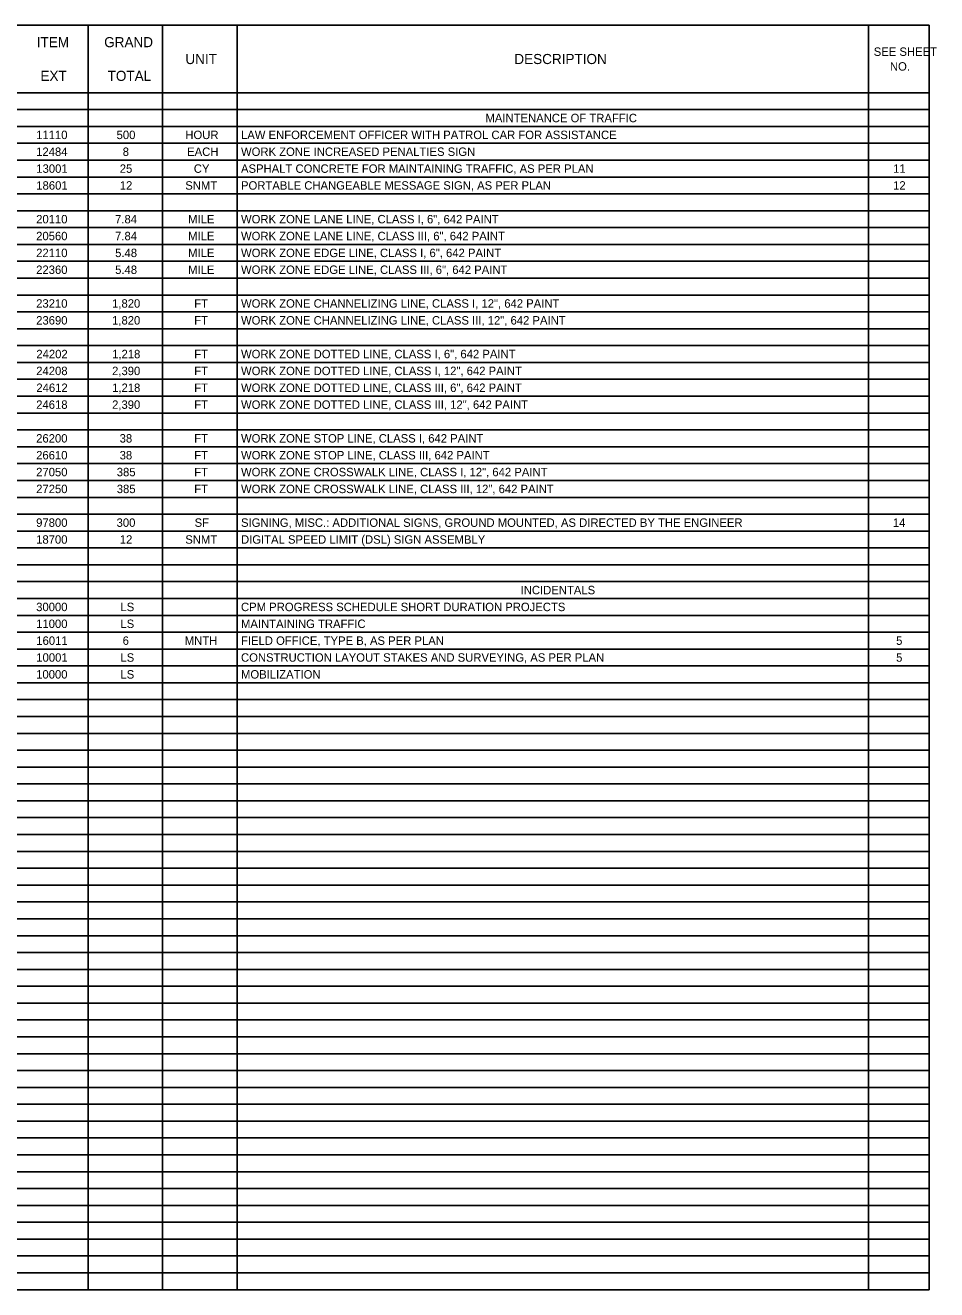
# Model space of a CAD drawing. Extents: x -32.2 to 34, y 0 to 22.
# Drawn here: x -16.7 to -1.56, y 0.5 to 21.5 of the extents above; entities that cross this region are included whole.
import ezdxf

# ---------------------------------------------------------------- set-up
doc = ezdxf.new("R2010")
doc.units = 0
doc.layers.add('SH_Text', color=7, linetype='Continuous')

msp = doc.modelspace()

# ---------------------------------------------------------------- linework, layer by layer
at = {"layer": 'SH_Text'}
for p, q in [((-32.188, 21.5), (-1.685, 21.5)), ((-15.652, 21.5), (-15.652, 0.5)), ((-14.417, 21.5), (-14.417, 0.5)), ((-13.181, 21.5), (-13.181, 0.5)), ((-2.69, 21.5), (-2.69, 0.5)), ((-1.685, 21.5), (-1.685, 0.5)), ((-32.188, 20.38), (-1.685, 20.38)), ((-32.188, 20.1), (-1.685, 20.1)), ((-32.188, 19.82), (-1.685, 19.82)), ((-32.188, 19.54), (-1.685, 19.54)), ((-32.188, 19.26), (-1.685, 19.26)), ((-32.188, 18.98), (-1.685, 18.98)), ((-32.188, 18.7), (-1.685, 18.7)), ((-32.188, 18.42), (-1.685, 18.42)), ((-32.188, 18.14), (-1.685, 18.14)), ((-32.188, 17.86), (-1.685, 17.86)), ((-32.188, 17.58), (-1.685, 17.58)), ((-32.188, 17.3), (-1.685, 17.3)), ((-32.188, 17.02), (-1.685, 17.02)), ((-32.188, 16.74), (-1.685, 16.74)), ((-32.188, 16.46), (-1.685, 16.46)), ((-32.188, 16.18), (-1.685, 16.18)), ((-32.188, 15.9), (-1.685, 15.9)), ((-32.188, 15.62), (-1.685, 15.62)), ((-32.188, 15.34), (-1.685, 15.34)), ((-32.188, 15.06), (-1.685, 15.06)), ((-32.188, 14.78), (-1.685, 14.78)), ((-32.188, 14.5), (-1.685, 14.5)), ((-32.188, 14.22), (-1.685, 14.22)), ((-32.188, 13.94), (-1.685, 13.94)), ((-32.188, 13.66), (-1.685, 13.66)), ((-32.188, 13.38), (-1.685, 13.38)), ((-32.188, 13.1), (-1.685, 13.1)), ((-32.188, 12.82), (-1.685, 12.82)), ((-32.188, 12.54), (-1.685, 12.54)), ((-32.188, 12.26), (-1.685, 12.26)), ((-32.188, 11.98), (-1.685, 11.98)), ((-32.188, 11.7), (-1.685, 11.7)), ((-32.188, 11.42), (-1.685, 11.42)), ((-32.188, 11.14), (-1.685, 11.14)), ((-32.188, 10.86), (-1.685, 10.86)), ((-32.188, 10.58), (-1.685, 10.58)), ((-32.188, 10.3), (-1.685, 10.3)), ((-32.188, 10.02), (-1.685, 10.02)), ((-32.188, 9.74), (-1.685, 9.74)), ((-32.188, 9.46), (-1.685, 9.46)), ((-32.188, 9.18), (-1.685, 9.18)), ((-32.188, 8.9), (-1.685, 8.9)), ((-32.188, 8.62), (-1.685, 8.62)), ((-32.188, 8.34), (-1.685, 8.34)), ((-32.188, 8.06), (-1.685, 8.06)), ((-32.188, 7.78), (-1.685, 7.78)), ((-32.188, 7.5), (-1.685, 7.5)), ((-32.188, 7.22), (-1.685, 7.22)), ((-32.188, 6.94), (-1.685, 6.94)), ((-32.188, 6.66), (-1.685, 6.66)), ((-32.188, 6.38), (-1.685, 6.38)), ((-32.188, 6.1), (-1.685, 6.1)), ((-32.188, 5.82), (-1.685, 5.82)), ((-32.188, 5.54), (-1.685, 5.54)), ((-32.188, 5.26), (-1.685, 5.26)), ((-32.188, 4.98), (-1.685, 4.98)), ((-32.188, 4.7), (-1.685, 4.7)), ((-32.188, 4.42), (-1.685, 4.42)), ((-32.188, 4.14), (-1.685, 4.14)), ((-32.188, 3.86), (-1.685, 3.86)), ((-32.188, 3.58), (-1.685, 3.58)), ((-32.188, 3.3), (-1.685, 3.3)), ((-32.188, 3.02), (-1.685, 3.02)), ((-32.188, 2.74), (-1.685, 2.74)), ((-32.188, 2.46), (-1.685, 2.46)), ((-32.188, 2.18), (-1.685, 2.18)), ((-32.188, 1.9), (-1.685, 1.9)), ((-32.188, 1.62), (-1.685, 1.62)), ((-32.188, 1.34), (-1.685, 1.34)), ((-32.188, 1.06), (-1.685, 1.06)), ((-32.188, 0.78), (-1.685, 0.78)), ((-32.188, 0.5), (-1.685, 0.5))]:
    msp.add_line(p, q, dxfattribs=at)

# ---------------------------------------------------------------- texts
for s, height, p in [('ITEM', 0.168, (-16.508, 21.136)), ('GRAND', 0.168, (-15.388, 21.136)), ('UNIT', 0.168, (-14.039, 20.856)), ('DESCRIPTION', 0.168, (-8.574, 20.856)), ('SEE SHEET ', 0.14, (-2.604, 20.992)), ('NO.', 0.14, (-2.335, 20.747)), ('EXT', 0.168, (-16.447, 20.576)), ('TOTAL', 0.168, (-15.331, 20.576)), ('MAINTENANCE OF TRAFFIC', 0.14, (-9.054, 19.89)), ('11110', 0.14, (-16.518, 19.61)), ('500', 0.14, (-15.182, 19.61)), ('HOUR', 0.14, (-14.04, 19.61)), ('LAW ENFORCEMENT OFFICER WITH PATROL CAR FOR ASSISTANCE', 0.14, (-13.115, 19.61)), ('12484', 0.14, (-16.518, 19.33)), ('8', 0.14, (-15.08, 19.33)), ('EACH', 0.14, (-14.01, 19.33)), ('WORK ZONE INCREASED PENALTIES SIGN', 0.14, (-13.115, 19.33)), ('13001', 0.14, (-16.516, 19.05)), ('25', 0.14, (-15.129, 19.05)), ('CY', 0.14, (-13.899, 19.05)), ('ASPHALT CONCRETE FOR MAINTAINING TRAFFIC, AS PER PLAN', 0.14, (-13.115, 19.05)), ('11', 0.14, (-2.282, 19.05)), ('18601', 0.14, (-16.516, 18.77)), ('12', 0.14, (-15.129, 18.77)), ('SNMT', 0.14, (-14.041, 18.77)), ('PORTABLE CHANGEABLE MESSAGE SIGN, AS PER PLAN', 0.14, (-13.115, 18.77)), ('12', 0.14, (-2.282, 18.77)), ('20110', 0.14, (-16.518, 18.21)), ('7.84', 0.14, (-15.207, 18.21)), ('MILE', 0.14, (-13.994, 18.21)), ('WORK ZONE LANE LINE, CLASS I, 6", 642 PAINT', 0.14, (-13.115, 18.21)), ('20560', 0.14, (-16.518, 17.93)), ('7.84', 0.14, (-15.207, 17.93)), ('MILE', 0.14, (-13.994, 17.93)), ('WORK ZONE LANE LINE, CLASS III, 6", 642 PAINT', 0.14, (-13.115, 17.93)), ('22110', 0.14, (-16.518, 17.65)), ('5.48', 0.14, (-15.206, 17.65)), ('MILE', 0.14, (-13.994, 17.65)), ('WORK ZONE EDGE LINE, CLASS I, 6", 642 PAINT', 0.14, (-13.115, 17.65)), ('22360', 0.14, (-16.518, 17.37)), ('5.48', 0.14, (-15.206, 17.37)), ('MILE', 0.14, (-13.994, 17.37)), ('WORK ZONE EDGE LINE, CLASS III, 6", 642 PAINT', 0.14, (-13.115, 17.37)), ('23210', 0.14, (-16.518, 16.81)), ('1,820', 0.14, (-15.257, 16.81)), ('FT', 0.14, (-13.892, 16.81)), ('WORK ZONE CHANNELIZING LINE, CLASS I, 12", 642 PAINT', 0.14, (-13.115, 16.81)), ('23690', 0.14, (-16.518, 16.53)), ('1,820', 0.14, (-15.257, 16.53)), ('FT', 0.14, (-13.892, 16.53)), ('WORK ZONE CHANNELIZING LINE, CLASS III, 12", 642 PAINT', 0.14, (-13.115, 16.53)), ('24202', 0.14, (-16.515, 15.97)), ('1,218', 0.14, (-15.256, 15.97)), ('FT', 0.14, (-13.892, 15.97)), ('WORK ZONE DOTTED LINE, CLASS I, 6", 642 PAINT', 0.14, (-13.115, 15.97)), ('24208', 0.14, (-16.517, 15.69)), ('2,390', 0.14, (-15.257, 15.69)), ('FT', 0.14, (-13.892, 15.69)), ('WORK ZONE DOTTED LINE, CLASS I, 12", 642 PAINT', 0.14, (-13.115, 15.69)), ('24612', 0.14, (-16.515, 15.41)), ('1,218', 0.14, (-15.256, 15.41)), ('FT', 0.14, (-13.892, 15.41)), ('WORK ZONE DOTTED LINE, CLASS III, 6", 642 PAINT', 0.14, (-13.115, 15.41)), ('24618', 0.14, (-16.517, 15.13)), ('2,390', 0.14, (-15.257, 15.13)), ('FT', 0.14, (-13.892, 15.13)), ('WORK ZONE DOTTED LINE, CLASS III, 12", 642 PAINT', 0.14, (-13.115, 15.13)), ('26200', 0.14, (-16.518, 14.57)), ('38', 0.14, (-15.131, 14.57)), ('FT', 0.14, (-13.892, 14.57)), ('WORK ZONE STOP LINE, CLASS I, 642 PAINT', 0.14, (-13.115, 14.57)), ('26610', 0.14, (-16.518, 14.29)), ('38', 0.14, (-15.131, 14.29)), ('FT', 0.14, (-13.892, 14.29)), ('WORK ZONE STOP LINE, CLASS III, 642 PAINT', 0.14, (-13.115, 14.29)), ('27050', 0.14, (-16.518, 14.01)), ('385', 0.14, (-15.179, 14.01)), ('FT', 0.14, (-13.892, 14.01)), ('WORK ZONE CROSSWALK LINE, CLASS I, 12", 642 PAINT', 0.14, (-13.115, 14.01)), ('27250', 0.14, (-16.518, 13.73)), ('385', 0.14, (-15.179, 13.73)), ('FT', 0.14, (-13.892, 13.73)), ('WORK ZONE CROSSWALK LINE, CLASS III, 12", 642 PAINT', 0.14, (-13.115, 13.73)), ('97800', 0.14, (-16.518, 13.17)), ('300', 0.14, (-15.182, 13.17)), ('SF', 0.14, (-13.886, 13.17)), ('SIGNING, MISC.: ADDITIONAL SIGNS, GROUND MOUNTED, AS DIRECTED BY THE ENGINEER', 0.14, (-13.115, 13.17)), ('14', 0.14, (-2.285, 13.17)), ('18700', 0.14, (-16.518, 12.89)), ('12', 0.14, (-15.129, 12.89)), ('SNMT', 0.14, (-14.041, 12.89)), ('DIGITAL SPEED LIMIT (DSL) SIGN ASSEMBLY', 0.14, (-13.115, 12.89)), ('INCIDENTALS', 0.14, (-8.47, 12.05)), ('30000', 0.14, (-16.518, 11.77)), ('LS', 0.14, (-15.118, 11.77)), ('CPM PROGRESS SCHEDULE SHORT DURATION PROJECTS', 0.14, (-13.115, 11.77)), ('11000', 0.14, (-16.518, 11.49)), ('LS', 0.14, (-15.118, 11.49)), ('MAINTAINING TRAFFIC', 0.14, (-13.115, 11.49)), ('16011', 0.14, (-16.516, 11.21)), ('6', 0.14, (-15.081, 11.21)), ('MNTH', 0.14, (-14.05, 11.21)), ('FIELD OFFICE, TYPE B, AS PER PLAN', 0.14, (-13.115, 11.21)), ('5', 0.14, (-2.232, 11.21)), ('10001', 0.14, (-16.516, 10.93)), ('LS', 0.14, (-15.118, 10.93)), ('CONSTRUCTION LAYOUT STAKES AND SURVEYING, AS PER PLAN', 0.14, (-13.115, 10.93)), ('5', 0.14, (-2.232, 10.93)), ('10000', 0.14, (-16.518, 10.65)), ('LS', 0.14, (-15.118, 10.65)), ('MOBILIZATION', 0.14, (-13.115, 10.65))]:
    msp.add_text(s, height=height, dxfattribs=at).set_placement(p)

doc.saveas('drawing.dxf')
